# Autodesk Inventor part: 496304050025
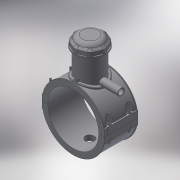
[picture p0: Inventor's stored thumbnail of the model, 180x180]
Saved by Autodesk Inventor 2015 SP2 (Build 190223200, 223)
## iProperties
Created: 2017-07
Part Number: 496304050025
Material: Generic
Description: PLASSON TAPPING SADDLE 50x25
Document SubType Name: Modeling
Designer: KIM
Mass: 169.301 g
Surface Area: 711.969 cm^2
Volume: 169.301 cm^3
Density: 1 g/cm^3
Appearance: Default
Author: KIM
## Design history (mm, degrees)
derived "496304.ipt"
feature "Solid1::496304.ipt"
feature "Solid2::496304.ipt"
feature "Solid4::496304.ipt"
feature "Solid5::496304.ipt"
tag "TaggingFeature1"
body "Solid1"
body "Solid2"
other parameters: "B_" = 76, "d_t" = 6, "H_2" = 98, "d_1" = 25, "H_" = 91, "d1" = 65, "d148" = 0.75, "d160" = 0.75, "d169" = 3.375, "d192" = 6.3, "d2" = 76, "d3" = 12.5, "d5" = 0, "d6" = 0.1, "d8" = 0, "d19" = 6, "d20" = 6, "d23" = 0, "d26" = 0, "d29" = 3, "d30" = 16.66667, "d31" = 6, "d32" = 0, "d33" = 0, "d34" = 0.6, "d40" = 33.8, "d41" = 45, "d43" = 0, "d45" = 0, "d47" = 92.5, "d70" = 15, "d72" = 0, "d73" = 6, "d75" = 5, "d76" = 0, "d77" = 2.5, "d78" = 55, "d79" = 15, "d82" = 5 deg, "d84" = 4, "d85" = 14, "d86" = 0, "d87" = 3, "d88" = 0, "d89" = 1, "d90" = 1, "d92" = 0, "d93" = 0.5, "d94" = 26.31579, "d96" = 66.3, "d97" = 2, "d98" = 0, "d102" = 0.5, "d120" = 140 deg, "d121" = 24.228, "d122" = 20 deg, "d124" = 39, "d126" = 0, "d143" = 51.5, "d145" = 11.53846, "d149" = 0.75, "d150" = 12.69231, "d154" = 0, "d156" = 32.5, "d157" = 160 deg, "d159" = 3, "d161" = 0.75, "d163" = 0, "d164" = 25, "d167" = 5, "d168" = 31.70732, "d170" = 3.375, "d172" = 0, "d173" = 1, "d175" = 25, "d176" = 20 deg, "d177" = 3.5, "d178" = 15, "d180" = 0, "d183" = 6, "d184" = 2.8, "d185" = 32.5, "d186" = 32.5, "d187" = 32.5, "d188" = 4.5, "d189" = 3.5, "d190" = 0, "d191" = 48.75, "d193" = 6.3, "d194" = 3.5, "d195" = 90 deg, "d197" = 0, "d199" = 0, "d200" = 7.5, "d202" = 0, "d203" = 98, "d204" = 42.75, "d205" = 31.5, "d206" = 38.25, "d207" = 73.5, "d208" = 76.44, "d209" = 91.14, "d210" = 38.7, "d211" = 45, "d212" = 36, "d213" = -2.25, "d216" = 0, "d217" = 5, "d218" = 5, "d219" = 1, "d224" = 0, "d230" = 3, "d233" = 6, "d236" = 38, "d238" = 6.02433, "d243" = 6, "d247" = 6, "d248" = 6, "d249" = 6, "d253" = 6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
